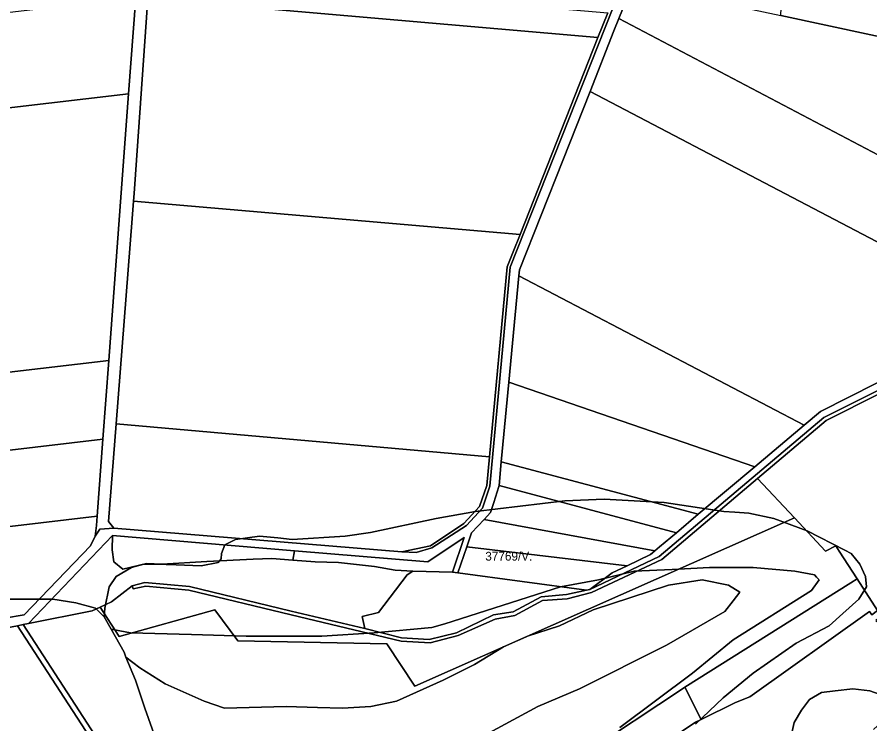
# Model space of a CAD drawing. Extents: x -541351 to -537540, y -1162694 to -1159725.
# Drawn here: x -538869.7 to -538384.7, y -1162096.9 to -1161694.8 of the extents above; entities that cross this region are included whole.
import ezdxf

# ---------------------------------------------------------------- set-up
doc = ezdxf.new("R2010")
doc.units = 0
for name, color, linetype in [('95560013', 7, 'Continuous'), ('95590013', 7, 'Continuous'), ('95600013', 7, 'Continuous'), ('95610013', 7, 'Continuous'), ('95630013', 7, 'Continuous'), ('95640013', 7, 'Continuous'), ('95660013', 7, 'Continuous')]:
    doc.layers.add(name, color=color, linetype=linetype)

msp = doc.modelspace()

# ---------------------------------------------------------------- linework, layer by layer
at = {"layer": '95560013'}
for points in [[(-538533.77, -1161692.37), (-538539.36, -1161706.5), (-538795.25, -1161683.97), (-538794.25, -1161669.79)], [(-538330.29, -1161716.49), (-538306.82, -1161717.74), (-538294.95, -1161718.38), (-538304.11, -1161813.16), (-538527.46, -1161695.68), (-538519.6, -1161675.81), (-538435.33, -1161693.92)], [(-539017.32, -1161708.72), (-538802.17, -1161683.57), (-538806.25, -1161738.46), (-539015.15, -1161763.02)], [(-538803.5, -1161799.61), (-538803.15, -1161795.11), (-538795.25, -1161683.97), (-538539.36, -1161706.5), (-538583.65, -1161818.41)], [(-538304.95, -1161821.22), (-538306.39, -1161834.98), (-538309.45, -1161848.88), (-538313.76, -1161857.67), (-538543.83, -1161737.06), (-538530.23, -1161702.68), (-538527.46, -1161695.68), (-538304.11, -1161813.16)], [(-539008.79, -1161912.59), (-539013.47, -1161803.39), (-539015.15, -1161763.02), (-538806.25, -1161738.46), (-538810.43, -1161794.77), (-538817.52, -1161890.24)], [(-538313.76, -1161857.67), (-538315.99, -1161861.59), (-538325.7, -1161872.5), (-538337.85, -1161880.5), (-538349.14, -1161886.93), (-538412.87, -1161919.25), (-538422.05, -1161926.97), (-538584.32, -1161841.97), (-538584.01, -1161838.63), (-538559.39, -1161776.37), (-538543.83, -1161737.06)], [(-538803.5, -1161799.61), (-538583.65, -1161818.41), (-538587.57, -1161828.3), (-538590.94, -1161836.83), (-538601, -1161944.96), (-538813.28, -1161926.27), (-538804.25, -1161809.32)], [(-538584.32, -1161841.97), (-538422.05, -1161926.97), (-538450.14, -1161950.59), (-538590.02, -1161902.5)], [(-539007.14, -1161951.05), (-539008.79, -1161912.59), (-538817.52, -1161890.24), (-538820.83, -1161934.92), (-539006.92, -1161956.95)], [(-538448.62, -1161957.3), (-538409.5, -1161924.28), (-538348.56, -1161893.55), (-538342.98, -1161890.59), (-538362.82, -1161931.77), (-538305.44, -1161982.77), (-538309.83, -1161994.08), (-538380.39, -1162032.29), (-538392, -1162014.33), (-538402.11, -1161998.67), (-538404.03, -1161995.59), (-538409.95, -1161998.61), (-538427.67, -1161979.68)], [(-538594.3, -1161947.9), (-538590.02, -1161902.5), (-538450.14, -1161950.59), (-538482.29, -1161977.62)], [(-538650.79, -1161999.07), (-538814.6, -1161985.57), (-538817.57, -1161981.7), (-538813.28, -1161926.27), (-538601, -1161944.96), (-538602.52, -1161961.34), (-538606.71, -1161973.27), (-538615.69, -1161982.82), (-538634.63, -1161995.5)], [(-538820.83, -1161934.92), (-538824.09, -1161978.8), (-539005.3, -1162000.22), (-539006.92, -1161956.95)], [(-538595.55, -1161961.24), (-538594.3, -1161947.9), (-538482.29, -1161977.62), (-538494.77, -1161988.11)], [(-538604.09, -1161980.62), (-538600.35, -1161976.7), (-538598.51, -1161970.95), (-538595.61, -1161961.84), (-538595.55, -1161961.24), (-538494.77, -1161988.11), (-538504.31, -1161996.13), (-538506.95, -1161998.35)]]:
    msp.add_lwpolyline(points, close=True, dxfattribs=at)
for points in [[(-539005.3, -1162000.22), (-538824.09, -1161978.8), (-538824.47, -1161983.94), (-538825.25, -1161990.14), (-538827.87, -1161995.55), (-538865.57, -1162034.76), (-538876.72, -1162036.74)], [(-538773.11, -1162183.87), (-538866.22, -1162040.39), (-538863.08, -1162039.76), (-538826.9, -1162032.51), (-538822.45, -1162030.47), (-538811.62, -1162047.08), (-538757.23, -1162032.03), (-538744.11, -1162049.59), (-538659.4, -1162051.33), (-538643.39, -1162075.45), (-538427.67, -1161979.68), (-538409.95, -1161998.61), (-538404.03, -1161995.59), (-538402.11, -1161998.67), (-538392, -1162014.33), (-538395.64, -1162016.62), (-538490, -1162076.05), (-538490.13, -1162076.14), (-538547.99, -1162114.54)], [(-538529.45, -1162126.6), (-538483.95, -1162095.95), (-538480.64, -1162094.32), (-538461.19, -1162084.75), (-538452.9, -1162081.47), (-538385, -1162032.87), (-538383.66, -1162034.91), (-538380.39, -1162032.29), (-538377.86, -1162035.24), (-538381.26, -1162037.97), (-538372.13, -1162045.7), (-538354.33, -1162052.73), (-538347.08, -1162059.2), (-538344.21, -1162061.76), (-538342.6, -1162063.19), (-538358.33, -1162077.66), (-538382.75, -1162100.13)], [(-538875.54, -1162042.25), (-538869.43, -1162041.03), (-538774.88, -1162186.74)]]:
    msp.add_lwpolyline(points, dxfattribs=at)
at = {"layer": '95590013'}
for points in [[(-538611.26, -1161988.13), (-538604.09, -1161980.62), (-538506.95, -1161998.35), (-538509.54, -1162000.53), (-538522.78, -1162007.03), (-538613.96, -1161996.08)], [(-538522.78, -1162007.03), (-538531.22, -1162010.94), (-538544.04, -1162020.34), (-538545.8, -1162020.73), (-538619, -1162010.95), (-538613.96, -1161996.08)]]:
    msp.add_lwpolyline(points, close=True, dxfattribs=at)
at = {"layer": '95600013'}
msp.add_lwpolyline([(-538598.67, -1162034.88), (-538619.76, -1162045.01), (-538635.3, -1162048.81), (-538651.07, -1162047.91), (-538671.98, -1162042.69), (-538673.38, -1162035.73), (-538664.06, -1162033.48), (-538647.92, -1162012.08), (-538644.52, -1162009.98), (-538621.98, -1162010.55), (-538619, -1162010.95), (-538545.8, -1162020.73), (-538557.2, -1162023.33), (-538571.7, -1162024.63), (-538587.5, -1162033.14)], close=True, dxfattribs=at)
at = {"layer": '95610013'}
for points in [[(-538618.79, -1162046.68), (-538597.81, -1162037.26), (-538586.69, -1162035.26), (-538570.89, -1162026.74), (-538556.83, -1162025.7), (-538543.06, -1162022.21), (-538503.11, -1162003.3), (-538448.62, -1161957.3), (-538427.67, -1161979.68), (-538643.39, -1162075.45), (-538659.4, -1162051.33), (-538744.11, -1162049.59), (-538757.23, -1162032.03), (-538811.62, -1162047.08), (-538822.45, -1162030.47), (-538816.04, -1162027.52), (-538804.26, -1162018.41), (-538803.58, -1162020.1), (-538796.41, -1162018.51), (-538772.02, -1162020.88), (-538713.86, -1162034.77), (-538651.26, -1162049.9), (-538634.78, -1162050.76)], [(-538826.9, -1162032.51), (-538863.08, -1162039.76), (-538815.36, -1161989.8), (-538815.6, -1161997.82), (-538814.62, -1162004.75), (-538809.53, -1162008.79), (-538795.97, -1162005.72), (-538787.27, -1162006.02), (-538761.72, -1162004.55), (-538735.45, -1162003.12), (-538724.76, -1162002.77), (-538712.81, -1162003.71), (-538700.14, -1162004.71), (-538686.84, -1162005.05), (-538666.36, -1162007.3), (-538654.65, -1162009.41), (-538644.52, -1162009.98), (-538647.92, -1162012.08), (-538664.06, -1162033.48), (-538673.38, -1162035.73), (-538671.98, -1162042.69), (-538713.73, -1162032.73), (-538771.54, -1162018.78), (-538797.02, -1162016.44), (-538804.26, -1162018.41), (-538816.04, -1162027.52), (-538822.45, -1162030.47)], [(-538724.76, -1162002.77), (-538735.45, -1162003.12), (-538761.72, -1162004.55), (-538787.27, -1162006.02), (-538795.97, -1162005.72), (-538809.53, -1162008.79), (-538814.62, -1162004.75), (-538815.6, -1161997.82), (-538815.36, -1161989.8), (-538711.96, -1161998.43), (-538712.81, -1162003.71)], [(-538395.64, -1162016.62), (-538392, -1162014.33), (-538380.39, -1162032.29), (-538383.66, -1162034.91), (-538385, -1162032.87), (-538452.9, -1162081.47), (-538461.19, -1162084.75), (-538480.64, -1162094.32), (-538490, -1162076.05)], [(-538483.95, -1162095.95), (-538529.45, -1162126.6), (-538544.72, -1162148.92), (-538552.35, -1162145.62), (-538567.4, -1162167.24), (-538575.5, -1162183.26), (-538597.29, -1162175.19), (-538584.08, -1162158.95), (-538547.99, -1162114.54), (-538490.13, -1162076.14), (-538490, -1162076.05), (-538480.64, -1162094.32)]]:
    msp.add_lwpolyline(points, close=True, dxfattribs=at)
at = {"layer": '95630013'}
for points in [[(-538472.42, -1161542.27), (-538589.29, -1161836.98), (-538600.78, -1161961.59), (-538605, -1161974.15), (-538614, -1161984.1), (-538633.82, -1161996.81), (-538642.69, -1161999.35), (-538650.79, -1161999.07), (-538634.63, -1161995.5), (-538615.69, -1161982.82), (-538606.71, -1161973.27), (-538602.52, -1161961.34), (-538601, -1161944.96), (-538590.94, -1161836.83), (-538587.57, -1161828.3), (-538583.65, -1161818.41), (-538539.36, -1161706.5), (-538533.77, -1161692.37)], [(-538348.56, -1161893.55), (-538409.5, -1161924.28), (-538448.62, -1161957.3), (-538503.11, -1162003.3), (-538543.06, -1162022.21), (-538556.83, -1162025.7), (-538570.89, -1162026.74), (-538586.69, -1162035.26), (-538597.81, -1162037.26), (-538618.79, -1162046.68), (-538634.78, -1162050.76), (-538651.26, -1162049.9), (-538713.86, -1162034.77), (-538772.02, -1162020.88), (-538796.41, -1162018.51), (-538803.58, -1162020.1), (-538804.26, -1162018.41), (-538797.02, -1162016.44), (-538771.54, -1162018.78), (-538713.73, -1162032.73), (-538671.98, -1162042.69), (-538651.07, -1162047.91), (-538635.3, -1162048.81), (-538619.76, -1162045.01), (-538598.67, -1162034.88), (-538587.5, -1162033.14), (-538571.7, -1162024.63), (-538557.2, -1162023.33), (-538545.8, -1162020.73), (-538544.04, -1162020.34), (-538504.49, -1162001.62), (-538410.88, -1161922.6), (-538347.4, -1161890.75)]]:
    msp.add_lwpolyline(points, dxfattribs=at)
at = {"layer": '95640013'}
for points in [[(-538876.72, -1162036.74), (-538865.57, -1162034.76), (-538827.87, -1161995.55), (-538825.25, -1161990.14), (-538822.66, -1161986.2), (-538814.6, -1161985.57), (-538650.79, -1161999.07), (-538642.69, -1161999.35), (-538633.82, -1161996.81), (-538614, -1161984.1), (-538605, -1161974.15), (-538600.78, -1161961.59), (-538589.29, -1161836.98), (-538472.42, -1161542.27)], [(-538519.6, -1161675.81), (-538527.46, -1161695.68), (-538530.23, -1161702.68), (-538543.83, -1161737.06), (-538559.39, -1161776.37), (-538584.01, -1161838.63), (-538584.32, -1161841.97), (-538590.02, -1161902.5), (-538594.3, -1161947.9), (-538595.55, -1161961.24), (-538595.61, -1161961.84), (-538598.51, -1161970.95), (-538600.35, -1161976.7), (-538604.09, -1161980.62), (-538611.26, -1161988.13), (-538613.96, -1161996.08), (-538619, -1162010.95), (-538621.98, -1162010.55), (-538615.41, -1161990.91), (-538636.08, -1162004.76), (-538711.96, -1161998.43), (-538815.36, -1161989.8), (-538863.08, -1162039.76), (-538866.22, -1162040.39), (-538869.43, -1162041.03), (-538875.54, -1162042.25)], [(-538795.25, -1161683.97), (-538803.15, -1161795.11), (-538803.5, -1161799.61), (-538804.25, -1161809.32), (-538813.28, -1161926.27), (-538817.57, -1161981.7), (-538814.6, -1161985.57), (-538822.66, -1161986.2), (-538825.25, -1161990.14), (-538824.47, -1161983.94), (-538824.09, -1161978.8), (-538820.83, -1161934.92), (-538817.52, -1161890.24), (-538810.43, -1161794.77), (-538806.25, -1161738.46), (-538802.17, -1161683.57)], [(-538347.4, -1161890.75), (-538410.88, -1161922.6), (-538504.49, -1162001.62), (-538544.04, -1162020.34), (-538531.22, -1162010.94), (-538522.78, -1162007.03), (-538509.54, -1162000.53), (-538506.95, -1161998.35), (-538504.31, -1161996.13), (-538494.77, -1161988.11), (-538482.29, -1161977.62), (-538450.14, -1161950.59), (-538422.05, -1161926.97), (-538412.87, -1161919.25), (-538349.14, -1161886.93)]]:
    msp.add_lwpolyline(points, dxfattribs=at)
for points in [[(-538294.95, -1161718.38), (-538306.82, -1161717.74), (-538330.29, -1161716.49), (-538435.33, -1161693.92), (-538431.86, -1161613.14), (-538404.54, -1161627.55), (-538406.26, -1161660.2), (-538395.47, -1161660.77), (-538394.01, -1161633.1), (-538356.05, -1161653.11), (-538357.53, -1161690.63), (-538345.04, -1161691.12), (-538343.79, -1161659.57), (-538322.38, -1161670.86), (-538323.5, -1161700.01), (-538312.75, -1161700.42), (-538311.83, -1161676.43), (-538291.91, -1161686.93)], [(-538711.96, -1161998.43), (-538636.08, -1162004.76), (-538615.41, -1161990.91), (-538621.98, -1162010.55), (-538644.52, -1162009.98), (-538654.65, -1162009.41), (-538666.36, -1162007.3), (-538686.84, -1162005.05), (-538700.14, -1162004.71), (-538712.81, -1162003.71)], [(-538774.88, -1162186.74), (-538869.43, -1162041.03), (-538866.22, -1162040.39), (-538773.11, -1162183.87)]]:
    msp.add_lwpolyline(points, close=True, dxfattribs=at)
at = {"layer": '95660013'}
for points in [[(-538483.81, -1162097), (-538468.19, -1162082), (-538451.12, -1162068), (-538426.62, -1162051), (-538407.87, -1162041), (-538400.19, -1162034), (-538391, -1162026), (-538386.62, -1162019), (-538387.12, -1162013), (-538390.37, -1162006), (-538395.37, -1162000), (-538399, -1161998), (-538420.31, -1161987), (-538439.37, -1161980), (-538453.62, -1161977), (-538461.44, -1161976.44), (-538467.69, -1161976), (-538501.69, -1161971), (-538535.81, -1161969), (-538558.12, -1161970), (-538609, -1161976), (-538631.37, -1161980), (-538668.69, -1161988), (-538683.12, -1161990), (-538713.31, -1161992), (-538721.37, -1161991), (-538731.87, -1161990), (-538745.5, -1161992), (-538751.5, -1161995), (-538753.31, -1162000), (-538753.62, -1162003), (-538755.31, -1162005), (-538764.87, -1162007), (-538779.21, -1162006.44), (-538790.69, -1162006), (-538797.5, -1162006), (-538804.62, -1162008), (-538813.31, -1162013), (-538817.31, -1162019), (-538819.81, -1162031), (-538820.19, -1162036), (-538825.12, -1162031), (-538836.31, -1162028), (-538849.37, -1162026), (-538883.31, -1162026)], [(-538526.87, -1162099), (-538485.62, -1162068), (-538462.5, -1162049), (-538417.87, -1162021), (-538413.62, -1162015), (-538415.05, -1162013.33), (-538416.19, -1162012), (-538427.31, -1162010), (-538451, -1162008), (-538476, -1162008), (-538497.12, -1162009), (-538518.69, -1162010), (-538539, -1162015), (-538560.62, -1162019), (-538626.37, -1162040), (-538633.81, -1162042), (-538666.5, -1162045), (-538696.37, -1162047), (-538717, -1162047), (-538739.37, -1162047), (-538770.37, -1162046), (-538805.12, -1162045), (-538811.27, -1162043.89), (-538816.19, -1162043), (-538820.19, -1162036), (-538819.81, -1162031), (-538817.31, -1162019), (-538813.31, -1162013), (-538804.62, -1162008), (-538797.5, -1162006), (-538790.69, -1162006), (-538779.21, -1162006.44), (-538764.87, -1162007), (-538755.31, -1162005), (-538753.62, -1162003), (-538753.31, -1162000), (-538751.5, -1161995), (-538745.5, -1161992), (-538731.87, -1161990), (-538721.37, -1161991), (-538713.31, -1161992), (-538683.12, -1161990), (-538668.69, -1161988), (-538631.37, -1161980), (-538609, -1161976), (-538558.12, -1161970), (-538535.81, -1161969), (-538501.69, -1161971), (-538467.69, -1161976), (-538461.44, -1161976.44), (-538453.62, -1161977), (-538439.37, -1161980), (-538420.31, -1161987), (-538399, -1161998), (-538395.37, -1162000), (-538390.37, -1162006), (-538387.12, -1162013), (-538386.62, -1162019), (-538391, -1162026), (-538400.19, -1162034), (-538407.87, -1162041), (-538426.62, -1162051), (-538451.12, -1162068), (-538468.19, -1162082), (-538483.81, -1162097)], [(-538610.69, -1162107), (-538573.62, -1162087), (-538549.81, -1162077), (-538500.31, -1162052), (-538467.12, -1162033), (-538462.44, -1162026.89), (-538458.69, -1162022), (-538465.19, -1162018), (-538480, -1162015), (-538499.31, -1162018), (-538542, -1162032), (-538561.19, -1162041), (-538579.37, -1162047), (-538593, -1162053), (-538609.5, -1162063), (-538627.37, -1162072), (-538653.81, -1162084), (-538668.5, -1162087), (-538684.69, -1162088), (-538698.88, -1162087.56), (-538716.62, -1162087), (-538751.69, -1162088), (-538763.31, -1162084), (-538785.5, -1162074), (-538799.81, -1162065), (-538807.81, -1162059), (-538808.81, -1162056), (-538816.19, -1162043), (-538811.27, -1162043.89), (-538805.12, -1162045), (-538770.37, -1162046), (-538739.37, -1162047), (-538717, -1162047), (-538696.37, -1162047), (-538666.5, -1162045), (-538633.81, -1162042), (-538626.37, -1162040), (-538560.62, -1162019), (-538539, -1162015), (-538518.69, -1162010), (-538497.12, -1162009), (-538476, -1162008), (-538451, -1162008), (-538427.31, -1162010), (-538416.19, -1162012), (-538415.05, -1162013.33), (-538413.62, -1162015), (-538417.87, -1162021), (-538462.5, -1162049), (-538485.62, -1162068), (-538526.87, -1162099)], [(-538787.62, -1162114), (-538797, -1162088), (-538802.37, -1162072), (-538807.81, -1162059), (-538799.81, -1162065), (-538785.5, -1162074), (-538763.31, -1162084), (-538751.69, -1162088), (-538716.62, -1162087), (-538698.88, -1162087.56), (-538684.69, -1162088), (-538668.5, -1162087), (-538653.81, -1162084), (-538627.37, -1162072), (-538609.5, -1162063), (-538593, -1162053), (-538579.37, -1162047), (-538561.19, -1162041), (-538542, -1162032), (-538499.31, -1162018), (-538480, -1162015), (-538465.19, -1162018), (-538458.69, -1162022), (-538462.44, -1162026.89), (-538467.12, -1162033), (-538500.31, -1162052), (-538549.81, -1162077), (-538573.62, -1162087), (-538610.69, -1162107)], [(-538883.31, -1162026), (-538849.37, -1162026), (-538836.31, -1162028), (-538825.12, -1162031), (-538820.19, -1162036), (-538816.19, -1162043), (-538808.81, -1162056), (-538807.81, -1162059), (-538802.37, -1162072), (-538797, -1162088), (-538787.62, -1162114)], [(-538429.31, -1162103), (-538427.81, -1162096), (-538423.62, -1162089), (-538419, -1162083), (-538412.19, -1162079), (-538404.5, -1162078), (-538394.37, -1162077), (-538384.81, -1162078), (-538376.81, -1162081), (-538366.62, -1162088), (-538358, -1162096), (-538350.62, -1162111)], [(-538350.62, -1162111), (-538358, -1162096), (-538366.62, -1162088), (-538376.81, -1162081), (-538384.81, -1162078), (-538394.37, -1162077), (-538404.5, -1162078), (-538412.19, -1162079), (-538419, -1162083), (-538423.62, -1162089), (-538427.81, -1162096), (-538429.31, -1162103)]]:
    msp.add_lwpolyline(points, dxfattribs=at)

# ---------------------------------------------------------------- texts
msp.add_text('37769/V.', height=5, rotation=0, dxfattribs=at).set_placement((-538603.41, -1162004))

doc.saveas('drawing.dxf')
